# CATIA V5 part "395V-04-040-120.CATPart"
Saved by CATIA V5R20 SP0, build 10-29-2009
Part number: 395V-04-040-120
Source: Unknown
Property "A": "0.000"
Property "ARTICLENO": "395V-04-040-120"
Property "BOMINFO": "395V-04-040-120"
Property "CODE": "395V-04-040-120"
Property "D": "32.000"
Property "D1": "18.000"
Property "D2": "26.000"
Property "D3": "50.000"
Property "FORM": "A"
Property "L": "120.000"
Property "L1": "16.000"
Property "L2": "46.000"
Property "L3": "32.000"
Property "L4": "10.000"
Property "LINA": "395V-04-040-120"
Property "MAXLOAD": "2000 Kg"
Property "MDW": "4000 Kg"
Property "NB": "395V-04-040-120"
Property "NBSYN": "$CODE."
Property "NN": "395V"
Property "NT": "VDI 3366 Lifting Brackets"
Property "SUPPLIER": "CF"
Property "T": "17.500"
Property "W": "40.000"
Bounding box of the stored display mesh (mm): x -20 to 20, y 0 to 120, z -20 to 20
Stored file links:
  C:\Users\Utente\Desktop\3D files 395V\395V-04-040-120.CATPart
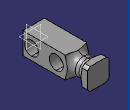
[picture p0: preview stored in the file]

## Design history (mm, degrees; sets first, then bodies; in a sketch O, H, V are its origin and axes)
Body1 "Geometry.1" (main body)
  Solid1 "395V-04-040-120.catpart": solid without history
